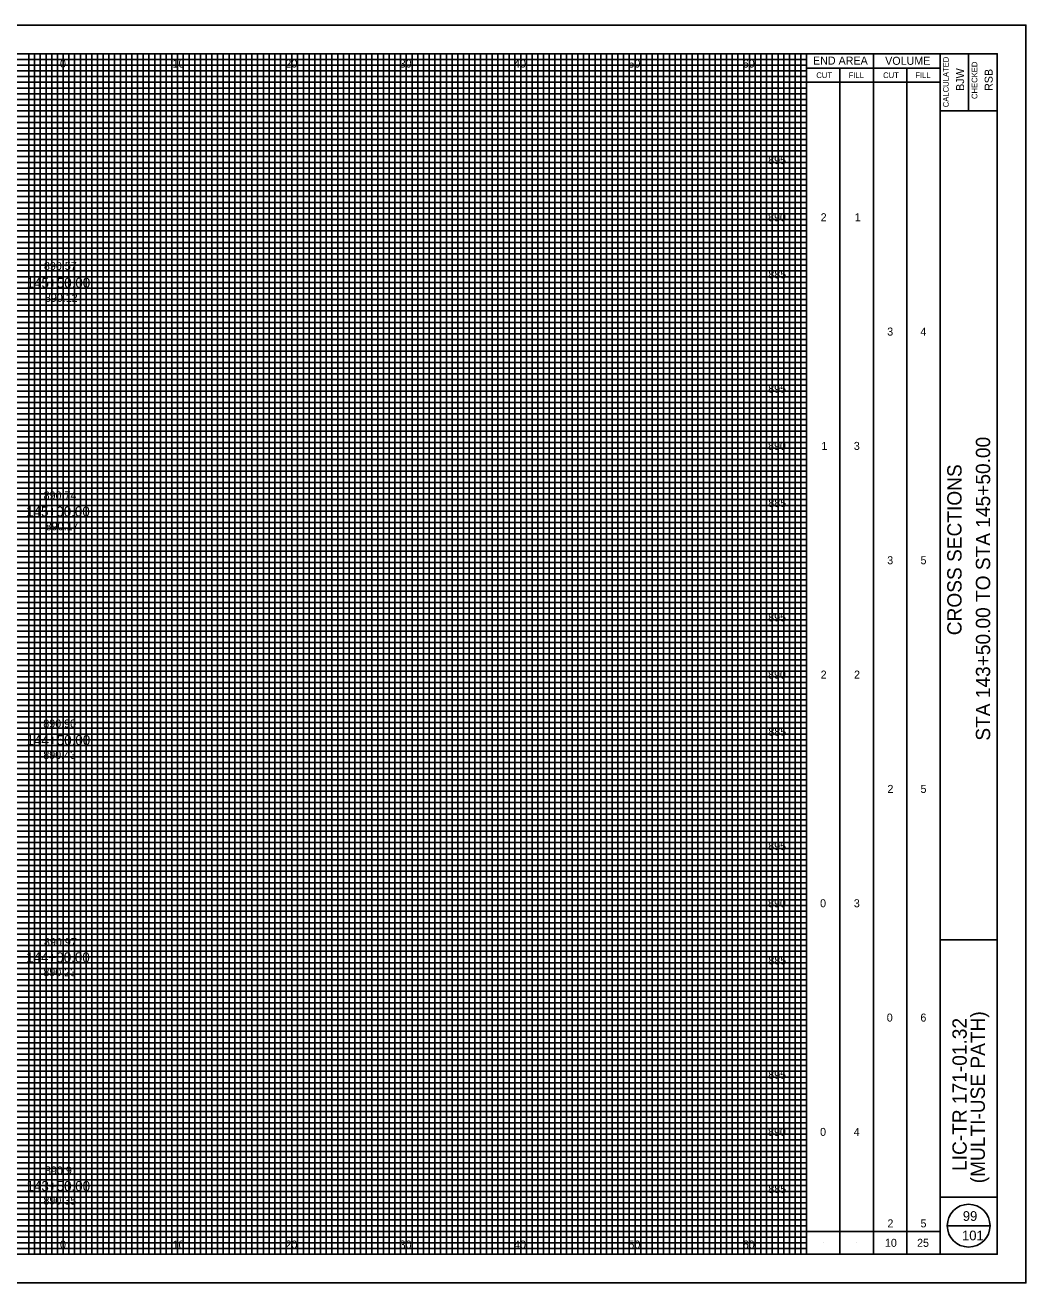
# Model space of a CAD drawing. Extents: x -10 to 160, y -2 to 3672.
# Drawn here: x 72.5 to 160, y 3447.5 to 3557.5 of the extents above; entities that cross this region are included whole.
import ezdxf

# ---------------------------------------------------------------- set-up
doc = ezdxf.new("R2010")
doc.units = 0
for name, color, linetype in [('SH_Border', 7, 'Continuous'), ('SH_Cut_Line', 7, 'Continuous'), ('SH_Data', 7, 'Continuous'), ('SH_Major_Grid_Line', 7, 'Continuous'), ('SH_Minor_Grid_Line', 7, 'Continuous'), ('SH_Text', 7, 'Continuous'), ('TX_P_10', 7, 'Continuous'), ('TX_X_10', 7, 'Continuous')]:
    doc.layers.add(name, color=color, linetype=linetype)

msp = doc.modelspace()

# ---------------------------------------------------------------- linework, layer by layer
at = {"layer": 'SH_Border'}
for p, q in [((152.5, 3450), (152.5, 3555)), ((155, 3555), (155, 3550)), ((152.5, 3550), (157.5, 3550)), ((152.5, 3477.5), (157.5, 3477.5)), ((152.5, 3455), (157.5, 3455))]:
    msp.add_line(p, q, dxfattribs=at)
msp.add_lwpolyline([(0, 3555), (157.5, 3555), (157.5, 3450), (0, 3450)], close=True, dxfattribs=at)
at = {"layer": 'SH_Cut_Line'}
msp.add_lwpolyline([(-10, 3447.5), (160, 3447.5), (160, 3557.5), (-10, 3557.5)], close=True, dxfattribs=at)
at = {"layer": 'SH_Data'}
for p, q in [((140.83, 3450), (140.83, 3555)), ((146.67, 3450), (146.67, 3555)), ((140.83, 3553.75), (152.5, 3553.75)), ((143.75, 3450), (143.75, 3553.75)), ((149.58, 3450), (149.58, 3553.75)), ((140.83, 3552.5), (152.5, 3552.5)), ((140.83, 3452), (152.5, 3452)), ((153.12, 3452.5), (156.88, 3452.5)), ((142.29, 3451), (142.29, 3451)), ((145.21, 3451), (145.21, 3451)), ((148.12, 3451), (148.12, 3451)), ((151.04, 3451), (151.04, 3451))]:
    msp.add_line(p, q, dxfattribs=at)
msp.add_circle((155, 3452.5), 1.87, dxfattribs=at)
at = {"layer": 'SH_Major_Grid_Line'}
for p, q in [((75.83, 3450), (75.83, 3555)), ((80.83, 3450), (80.83, 3555)), ((85.83, 3450), (85.83, 3555)), ((90.83, 3450), (90.83, 3555)), ((95.83, 3450), (95.83, 3555)), ((100.83, 3450), (100.83, 3555)), ((105.83, 3450), (105.83, 3555)), ((110.83, 3450), (110.83, 3555)), ((115.83, 3450), (115.83, 3555)), ((120.83, 3450), (120.83, 3555)), ((125.83, 3450), (125.83, 3555)), ((130.83, 3450), (130.83, 3555)), ((135.83, 3450), (135.83, 3555)), ((5.83, 3550), (140.83, 3550)), ((5.83, 3545), (140.83, 3545)), ((5.83, 3540), (140.83, 3540)), ((5.83, 3535), (140.83, 3535)), ((5.83, 3530), (140.83, 3530)), ((5.83, 3525), (140.83, 3525)), ((5.83, 3520), (140.83, 3520)), ((5.83, 3515), (140.83, 3515)), ((5.83, 3510), (140.83, 3510)), ((5.83, 3505), (140.83, 3505)), ((5.83, 3500), (140.83, 3500)), ((5.83, 3495), (140.83, 3495)), ((5.83, 3490), (140.83, 3490)), ((5.83, 3485), (140.83, 3485)), ((5.83, 3480), (140.83, 3480)), ((5.83, 3475), (140.83, 3475)), ((5.83, 3470), (140.83, 3470)), ((5.83, 3465), (140.83, 3465)), ((5.83, 3460), (140.83, 3460)), ((5.83, 3455), (140.83, 3455))]:
    msp.add_line(p, q, dxfattribs=at)
at = {"layer": 'SH_Minor_Grid_Line'}
for p, q in [((5.83, 3554.5), (140.83, 3554.5)), ((72.83, 3450), (72.83, 3555)), ((73.33, 3450), (73.33, 3555)), ((73.83, 3450), (73.83, 3555)), ((74.33, 3450), (74.33, 3555)), ((74.83, 3450), (74.83, 3555)), ((75.33, 3450), (75.33, 3555)), ((76.33, 3450), (76.33, 3555)), ((76.83, 3450), (76.83, 3555)), ((77.33, 3450), (77.33, 3555)), ((77.83, 3450), (77.83, 3555)), ((78.33, 3450), (78.33, 3555)), ((78.83, 3450), (78.83, 3555)), ((79.33, 3450), (79.33, 3555)), ((79.83, 3450), (79.83, 3555)), ((80.33, 3450), (80.33, 3555)), ((81.33, 3450), (81.33, 3555)), ((81.83, 3450), (81.83, 3555)), ((82.33, 3450), (82.33, 3555)), ((82.83, 3450), (82.83, 3555)), ((83.33, 3450), (83.33, 3555)), ((83.83, 3450), (83.83, 3555)), ((84.33, 3450), (84.33, 3555)), ((84.83, 3450), (84.83, 3555)), ((85.33, 3450), (85.33, 3555)), ((86.33, 3450), (86.33, 3555)), ((86.83, 3450), (86.83, 3555)), ((87.33, 3450), (87.33, 3555)), ((87.83, 3450), (87.83, 3555)), ((88.33, 3450), (88.33, 3555)), ((88.83, 3450), (88.83, 3555)), ((89.33, 3450), (89.33, 3555)), ((89.83, 3450), (89.83, 3555)), ((90.33, 3450), (90.33, 3555)), ((91.33, 3450), (91.33, 3555)), ((91.83, 3450), (91.83, 3555)), ((92.33, 3450), (92.33, 3555)), ((92.83, 3450), (92.83, 3555)), ((93.33, 3450), (93.33, 3555)), ((93.83, 3450), (93.83, 3555)), ((94.33, 3450), (94.33, 3555)), ((94.83, 3450), (94.83, 3555)), ((95.33, 3450), (95.33, 3555)), ((96.33, 3450), (96.33, 3555)), ((96.83, 3450), (96.83, 3555)), ((97.33, 3450), (97.33, 3555)), ((97.83, 3450), (97.83, 3555)), ((98.33, 3450), (98.33, 3555)), ((98.83, 3450), (98.83, 3555)), ((99.33, 3450), (99.33, 3555)), ((99.83, 3450), (99.83, 3555)), ((100.33, 3450), (100.33, 3555)), ((101.33, 3450), (101.33, 3555)), ((101.83, 3450), (101.83, 3555)), ((102.33, 3450), (102.33, 3555)), ((102.83, 3450), (102.83, 3555)), ((103.33, 3450), (103.33, 3555)), ((103.83, 3450), (103.83, 3555)), ((104.33, 3450), (104.33, 3555)), ((104.83, 3450), (104.83, 3555)), ((105.33, 3450), (105.33, 3555)), ((106.33, 3450), (106.33, 3555)), ((106.83, 3450), (106.83, 3555)), ((107.33, 3450), (107.33, 3555)), ((107.83, 3450), (107.83, 3555)), ((108.33, 3450), (108.33, 3555)), ((108.83, 3450), (108.83, 3555)), ((109.33, 3450), (109.33, 3555)), ((109.83, 3450), (109.83, 3555)), ((110.33, 3450), (110.33, 3555)), ((111.33, 3450), (111.33, 3555)), ((111.83, 3450), (111.83, 3555)), ((112.33, 3450), (112.33, 3555)), ((112.83, 3450), (112.83, 3555)), ((113.33, 3450), (113.33, 3555)), ((113.83, 3450), (113.83, 3555)), ((114.33, 3450), (114.33, 3555)), ((114.83, 3450), (114.83, 3555)), ((115.33, 3450), (115.33, 3555)), ((116.33, 3450), (116.33, 3555)), ((116.83, 3450), (116.83, 3555)), ((117.33, 3450), (117.33, 3555)), ((117.83, 3450), (117.83, 3555)), ((118.33, 3450), (118.33, 3555)), ((118.83, 3450), (118.83, 3555)), ((119.33, 3450), (119.33, 3555)), ((119.83, 3450), (119.83, 3555)), ((120.33, 3450), (120.33, 3555)), ((121.33, 3450), (121.33, 3555)), ((121.83, 3450), (121.83, 3555)), ((122.33, 3450), (122.33, 3555)), ((122.83, 3450), (122.83, 3555)), ((123.33, 3450), (123.33, 3555)), ((123.83, 3450), (123.83, 3555)), ((124.33, 3450), (124.33, 3555)), ((124.83, 3450), (124.83, 3555)), ((125.33, 3450), (125.33, 3555)), ((126.33, 3450), (126.33, 3555)), ((126.83, 3450), (126.83, 3555)), ((127.33, 3450), (127.33, 3555)), ((127.83, 3450), (127.83, 3555)), ((128.33, 3450), (128.33, 3555)), ((128.83, 3450), (128.83, 3555)), ((129.33, 3450), (129.33, 3555)), ((129.83, 3450), (129.83, 3555)), ((130.33, 3450), (130.33, 3555)), ((131.33, 3450), (131.33, 3555)), ((131.83, 3450), (131.83, 3555)), ((132.33, 3450), (132.33, 3555)), ((132.83, 3450), (132.83, 3555)), ((133.33, 3450), (133.33, 3555)), ((133.83, 3450), (133.83, 3555)), ((134.33, 3450), (134.33, 3555)), ((134.83, 3450), (134.83, 3555)), ((135.33, 3450), (135.33, 3555)), ((136.33, 3450), (136.33, 3555)), ((136.83, 3450), (136.83, 3555)), ((137.33, 3450), (137.33, 3555)), ((137.83, 3450), (137.83, 3555)), ((138.33, 3450), (138.33, 3555)), ((138.83, 3450), (138.83, 3555)), ((139.33, 3450), (139.33, 3555)), ((139.83, 3450), (139.83, 3555)), ((140.33, 3450), (140.33, 3555)), ((5.83, 3554), (140.83, 3554)), ((5.83, 3553.5), (140.83, 3553.5)), ((5.83, 3553), (140.83, 3553)), ((5.83, 3552.5), (140.83, 3552.5)), ((5.83, 3552), (140.83, 3552)), ((5.83, 3551.5), (140.83, 3551.5)), ((5.83, 3551), (140.83, 3551)), ((5.83, 3550.5), (140.83, 3550.5)), ((5.83, 3549.5), (140.83, 3549.5)), ((5.83, 3549), (140.83, 3549)), ((5.83, 3548.5), (140.83, 3548.5)), ((5.83, 3548), (140.83, 3548)), ((5.83, 3547.5), (140.83, 3547.5)), ((5.83, 3547), (140.83, 3547)), ((5.83, 3546.5), (140.83, 3546.5)), ((5.83, 3546), (140.83, 3546)), ((5.83, 3545.5), (140.83, 3545.5)), ((5.83, 3544.5), (140.83, 3544.5)), ((5.83, 3544), (140.83, 3544)), ((5.83, 3543.5), (140.83, 3543.5)), ((5.83, 3543), (140.83, 3543)), ((5.83, 3542.5), (140.83, 3542.5)), ((5.83, 3542), (140.83, 3542)), ((5.83, 3541.5), (140.83, 3541.5)), ((5.83, 3541), (140.83, 3541)), ((5.83, 3540.5), (140.83, 3540.5)), ((5.83, 3539.5), (140.83, 3539.5)), ((5.83, 3539), (140.83, 3539)), ((5.83, 3538.5), (140.83, 3538.5)), ((5.83, 3538), (140.83, 3538)), ((5.83, 3537.5), (140.83, 3537.5)), ((5.83, 3537), (140.83, 3537)), ((5.83, 3536.5), (140.83, 3536.5)), ((5.83, 3536), (140.83, 3536)), ((5.83, 3535.5), (140.83, 3535.5)), ((5.83, 3534.5), (140.83, 3534.5)), ((5.83, 3534), (140.83, 3534)), ((5.83, 3533.5), (140.83, 3533.5)), ((5.83, 3533), (140.83, 3533)), ((5.83, 3532.5), (140.83, 3532.5)), ((5.83, 3532), (140.83, 3532)), ((5.83, 3531.5), (140.83, 3531.5)), ((5.83, 3531), (140.83, 3531)), ((5.83, 3530.5), (140.83, 3530.5)), ((5.83, 3529.5), (140.83, 3529.5)), ((5.83, 3529), (140.83, 3529)), ((5.83, 3528.5), (140.83, 3528.5)), ((5.83, 3528), (140.83, 3528)), ((5.83, 3527.5), (140.83, 3527.5)), ((5.83, 3527), (140.83, 3527)), ((5.83, 3526.5), (140.83, 3526.5)), ((5.83, 3526), (140.83, 3526)), ((5.83, 3525.5), (140.83, 3525.5)), ((5.83, 3524.5), (140.83, 3524.5)), ((5.83, 3524), (140.83, 3524)), ((5.83, 3523.5), (140.83, 3523.5)), ((5.83, 3523), (140.83, 3523)), ((5.83, 3522.5), (140.83, 3522.5)), ((5.83, 3522), (140.83, 3522)), ((5.83, 3521.5), (140.83, 3521.5)), ((5.83, 3521), (140.83, 3521)), ((5.83, 3520.5), (140.83, 3520.5)), ((5.83, 3519.5), (140.83, 3519.5)), ((5.83, 3519), (140.83, 3519)), ((5.83, 3518.5), (140.83, 3518.5)), ((5.83, 3518), (140.83, 3518)), ((5.83, 3517.5), (140.83, 3517.5)), ((5.83, 3517), (140.83, 3517)), ((5.83, 3516.5), (140.83, 3516.5)), ((5.83, 3516), (140.83, 3516)), ((5.83, 3515.5), (140.83, 3515.5)), ((5.83, 3514.5), (140.83, 3514.5)), ((5.83, 3514), (140.83, 3514)), ((5.83, 3513.5), (140.83, 3513.5)), ((5.83, 3513), (140.83, 3513)), ((5.83, 3512.5), (140.83, 3512.5)), ((5.83, 3512), (140.83, 3512)), ((5.83, 3511.5), (140.83, 3511.5)), ((5.83, 3511), (140.83, 3511)), ((5.83, 3510.5), (140.83, 3510.5)), ((5.83, 3509.5), (140.83, 3509.5)), ((5.83, 3509), (140.83, 3509)), ((5.83, 3508.5), (140.83, 3508.5)), ((5.83, 3508), (140.83, 3508)), ((5.83, 3507.5), (140.83, 3507.5)), ((5.83, 3507), (140.83, 3507)), ((5.83, 3506.5), (140.83, 3506.5)), ((5.83, 3506), (140.83, 3506)), ((5.83, 3505.5), (140.83, 3505.5)), ((5.83, 3504.5), (140.83, 3504.5)), ((5.83, 3504), (140.83, 3504)), ((5.83, 3503.5), (140.83, 3503.5)), ((5.83, 3503), (140.83, 3503)), ((5.83, 3502.5), (140.83, 3502.5)), ((5.83, 3502), (140.83, 3502)), ((5.83, 3501.5), (140.83, 3501.5)), ((5.83, 3501), (140.83, 3501)), ((5.83, 3500.5), (140.83, 3500.5)), ((5.83, 3499.5), (140.83, 3499.5)), ((5.83, 3499), (140.83, 3499)), ((5.83, 3498.5), (140.83, 3498.5)), ((5.83, 3498), (140.83, 3498)), ((5.83, 3497.5), (140.83, 3497.5)), ((5.83, 3497), (140.83, 3497)), ((5.83, 3496.5), (140.83, 3496.5)), ((5.83, 3496), (140.83, 3496)), ((5.83, 3495.5), (140.83, 3495.5)), ((5.83, 3494.5), (140.83, 3494.5)), ((5.83, 3494), (140.83, 3494)), ((5.83, 3493.5), (140.83, 3493.5)), ((5.83, 3493), (140.83, 3493)), ((5.83, 3492.5), (140.83, 3492.5)), ((5.83, 3492), (140.83, 3492)), ((5.83, 3491.5), (140.83, 3491.5)), ((5.83, 3491), (140.83, 3491)), ((5.83, 3490.5), (140.83, 3490.5)), ((5.83, 3489.5), (140.83, 3489.5)), ((5.83, 3489), (140.83, 3489)), ((5.83, 3488.5), (140.83, 3488.5)), ((5.83, 3488), (140.83, 3488)), ((5.83, 3487.5), (140.83, 3487.5)), ((5.83, 3487), (140.83, 3487)), ((5.83, 3486.5), (140.83, 3486.5)), ((5.83, 3486), (140.83, 3486)), ((5.83, 3485.5), (140.83, 3485.5)), ((5.83, 3484.5), (140.83, 3484.5)), ((5.83, 3484), (140.83, 3484)), ((5.83, 3483.5), (140.83, 3483.5)), ((5.83, 3483), (140.83, 3483)), ((5.83, 3482.5), (140.83, 3482.5)), ((5.83, 3482), (140.83, 3482)), ((5.83, 3481.5), (140.83, 3481.5)), ((5.83, 3481), (140.83, 3481)), ((5.83, 3480.5), (140.83, 3480.5)), ((5.83, 3479.5), (140.83, 3479.5)), ((5.83, 3479), (140.83, 3479)), ((5.83, 3478.5), (140.83, 3478.5)), ((5.83, 3478), (140.83, 3478)), ((5.83, 3477.5), (140.83, 3477.5)), ((5.83, 3477), (140.83, 3477)), ((5.83, 3476.5), (140.83, 3476.5)), ((5.83, 3476), (140.83, 3476)), ((5.83, 3475.5), (140.83, 3475.5)), ((5.83, 3474.5), (140.83, 3474.5)), ((5.83, 3474), (140.83, 3474)), ((5.83, 3473.5), (140.83, 3473.5)), ((5.83, 3473), (140.83, 3473)), ((5.83, 3472.5), (140.83, 3472.5)), ((5.83, 3472), (140.83, 3472)), ((5.83, 3471.5), (140.83, 3471.5)), ((5.83, 3471), (140.83, 3471)), ((5.83, 3470.5), (140.83, 3470.5)), ((5.83, 3469.5), (140.83, 3469.5)), ((5.83, 3469), (140.83, 3469)), ((5.83, 3468.5), (140.83, 3468.5)), ((5.83, 3468), (140.83, 3468)), ((5.83, 3467.5), (140.83, 3467.5)), ((5.83, 3467), (140.83, 3467)), ((5.83, 3466.5), (140.83, 3466.5)), ((5.83, 3466), (140.83, 3466)), ((5.83, 3465.5), (140.83, 3465.5)), ((5.83, 3464.5), (140.83, 3464.5)), ((5.83, 3464), (140.83, 3464)), ((5.83, 3463.5), (140.83, 3463.5)), ((5.83, 3463), (140.83, 3463)), ((5.83, 3462.5), (140.83, 3462.5)), ((5.83, 3462), (140.83, 3462)), ((5.83, 3461.5), (140.83, 3461.5)), ((5.83, 3461), (140.83, 3461)), ((5.83, 3460.5), (140.83, 3460.5)), ((5.83, 3459.5), (140.83, 3459.5)), ((5.83, 3459), (140.83, 3459)), ((5.83, 3458.5), (140.83, 3458.5)), ((5.83, 3458), (140.83, 3458)), ((5.83, 3457.5), (140.83, 3457.5)), ((5.83, 3457), (140.83, 3457)), ((5.83, 3456.5), (140.83, 3456.5)), ((5.83, 3456), (140.83, 3456)), ((5.83, 3455.5), (140.83, 3455.5)), ((5.83, 3454.5), (140.83, 3454.5)), ((5.83, 3454), (140.83, 3454)), ((5.83, 3453.5), (140.83, 3453.5)), ((5.83, 3453), (140.83, 3453)), ((5.83, 3452.5), (140.83, 3452.5)), ((5.83, 3452), (140.83, 3452)), ((5.83, 3451.5), (140.83, 3451.5)), ((5.83, 3451), (140.83, 3451)), ((5.83, 3450.5), (140.83, 3450.5))]:
    msp.add_line(p, q, dxfattribs=at)

# ---------------------------------------------------------------- texts
at = {"layer": 'SH_Data'}
for s, height, p in [('END AREA', 0.7, (141.39, 3554.05)), ('VOLUME', 0.7, (147.7, 3554.03)), ('CUT', 0.5, (141.68, 3552.87)), ('FILL', 0.5, (144.5, 3552.87)), ('CUT', 0.5, (147.52, 3552.87)), ('FILL', 0.5, (150.34, 3552.87)), ('99', 0.85, (154.49, 3452.92)), ('101', 0.85, (154.42, 3451.22))]:
    msp.add_text(s, height=height, dxfattribs=at).set_placement(p)
for s, height, p in [('CALCULATED', 0.5, (153.26, 3550.32)), ('CHECKED', 0.5, (155.76, 3551.04)), ('BJW', 0.7, (154.6, 3551.75)), ('RSB', 0.7, (157.1, 3551.75)), ('STA 143+50.00 TO STA 145+50.00', 1.25, (156.88, 3494.92)), ('CROSS SECTIONS', 1.25, (154.38, 3504.14)), ('LIC-TR 171-01.32', 1.25, (154.83, 3457.29)), ('(MULTI-USE PATH)', 1.25, (156.42, 3456.21))]:
    msp.add_text(s, height=height, rotation=90, dxfattribs=at).set_placement(p)
at = {"layer": 'SH_Text'}
for s, height, p in [('0', 0.7, (75.55, 3553.79)), ('10', 0.7, (85.39, 3553.79)), ('20', 0.7, (95.26, 3553.79)), ('30', 0.7, (105.25, 3553.79)), ('40', 0.7, (115.25, 3553.79)), ('50', 0.7, (125.25, 3553.79)), ('60', 0.7, (135.25, 3553.79)), ('895', 0.7, (137.47, 3545.35)), ('890', 0.7, (137.46, 3540.35)), ('2', 0.7, (142.06, 3540.35)), ('1', 0.7, (145.04, 3540.35)), ('145+50.00', 0.875, (72.63, 3534.53)), ('885', 0.7, (137.48, 3535.35)), ('3', 0.7, (147.88, 3530.35)), ('4', 0.7, (150.78, 3530.35)), ('895', 0.7, (137.47, 3525.35)), ('890', 0.7, (137.46, 3520.35)), ('1', 0.7, (142.13, 3520.35)), ('3', 0.7, (144.96, 3520.35)), ('885', 0.7, (137.48, 3515.35)), ('145+00.00', 0.875, (72.59, 3514.53)), ('3', 0.7, (147.88, 3510.35)), ('5', 0.7, (150.79, 3510.35)), ('895', 0.7, (137.47, 3505.35)), ('890', 0.7, (137.46, 3500.35)), ('2', 0.7, (142.06, 3500.35)), ('2', 0.7, (144.98, 3500.35)), ('885', 0.7, (137.48, 3495.35)), ('144+50.00', 0.875, (72.63, 3494.53)), ('2', 0.7, (147.9, 3490.35)), ('5', 0.7, (150.79, 3490.35)), ('895', 0.7, (137.47, 3485.35)), ('890', 0.7, (137.46, 3480.35)), ('0', 0.7, (142.01, 3480.35)), ('3', 0.7, (144.96, 3480.35)), ('144+00.00', 0.875, (72.59, 3475.53)), ('885', 0.7, (137.48, 3475.35)), ('0', 0.7, (147.84, 3470.35)), ('6', 0.7, (150.78, 3470.35)), ('895', 0.7, (137.47, 3465.35)), ('890', 0.7, (137.46, 3460.35)), ('0', 0.7, (142.01, 3460.35)), ('4', 0.7, (144.95, 3460.35)), ('143+50.00', 0.875, (72.62, 3455.53)), ('885', 0.7, (137.48, 3455.35)), ('2', 0.7, (147.9, 3452.35)), ('5', 0.7, (150.79, 3452.35)), ('0', 0.7, (75.55, 3450.5)), ('10', 0.7, (85.39, 3450.5)), ('20', 0.7, (95.26, 3450.5)), ('30', 0.7, (105.25, 3450.5)), ('40', 0.7, (115.25, 3450.5)), ('50', 0.7, (125.25, 3450.5)), ('60', 0.7, (135.25, 3450.5)), ('10', 0.7, (147.68, 3450.65)), ('25', 0.7, (150.49, 3450.65))]:
    msp.add_text(s, height=height, dxfattribs=at).set_placement(p)
at = {"layer": 'TX_P_10'}
for s, p in [('890.57', (74.15, 3536.09)), ('890.74', (74.12, 3516.02)), ('890.90', (74.09, 3496.07)), ('890.97', (74.15, 3476.96)), ('890.91', (74.24, 3456.98))]:
    msp.add_text(s, height=0.7, dxfattribs=at).set_placement(p)
at = {"layer": 'TX_X_10'}
for s, p in [('890.12', (74.23, 3533.3)), ('890.17', (74.3, 3513.32)), ('890.43', (74.09, 3493.32)), ('890.23', (74.1, 3474.32)), ('890.35', (74.1, 3454.35))]:
    msp.add_text(s, height=0.7, dxfattribs=at).set_placement(p)

doc.saveas('drawing.dxf')
